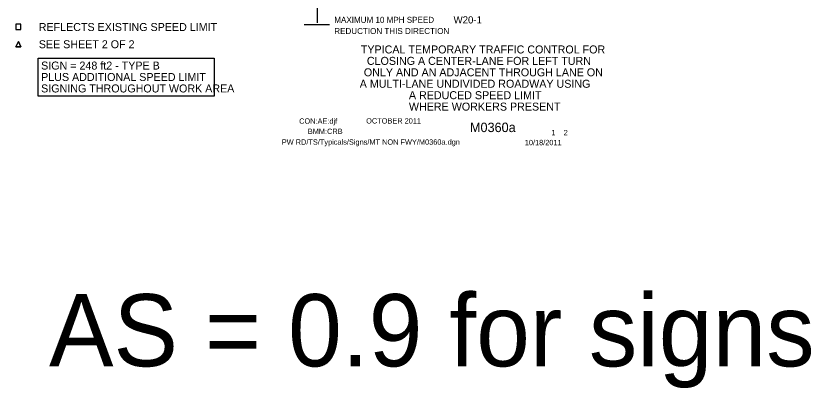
# Model space of a CAD drawing. Extents: x 16730 to 18475, y 5651 to 6927.
# Drawn here: x 16762 to 17686, y 5651 to 6084 of the extents above; entities that cross this region are included whole.
import ezdxf

# ---------------------------------------------------------------- set-up
doc = ezdxf.new("R2010")
doc.units = 0
for name, color, linetype in [('BORDER_SIGNAL_WO', 7, 'Continuous'), ('TRAFFIC_SIGNS_PR', 7, 'Continuous'), ('TYPICAL_TEXT_DIMEN_EX', 7, 'Continuous'), ('TYPICAL_TEXT_DIMEN_PR', 7, 'Continuous')]:
    doc.layers.add(name, color=color, linetype=linetype)

msp = doc.modelspace()

# ---------------------------------------------------------------- linework, layer by layer
at = {"layer": 'TRAFFIC_SIGNS_PR'}
msp.add_lwpolyline([(16761.51, 6067.78), (16767.11, 6067.78), (16767.11, 6073.95), (16761.51, 6073.95)], close=True, dxfattribs=at)
for points in [[(16764.35, 6053.92), (16761.56, 6047.75)], [(16761.56, 6047.75), (16764.35, 6053.92)], [(16767.15, 6047.75), (16764.35, 6053.92)], [(16764.35, 6053.92), (16767.15, 6047.75)], [(16761.56, 6047.75), (16767.15, 6047.75)], [(16767.15, 6047.75), (16761.56, 6047.75)]]:
    msp.add_lwpolyline(points, dxfattribs=at)
at = {"layer": 'TYPICAL_TEXT_DIMEN_EX'}
msp.add_lwpolyline([(16787.48, 6034.22), (16991.76, 6034.22), (16991.76, 5990.25), (16787.48, 5990.25)], close=True, dxfattribs=at)
at = {"layer": 'TYPICAL_TEXT_DIMEN_PR'}
for p, q in [((17111.86, 6075.55), (17111.86, 6092.68)), ((17126.03, 6073.05), (17096.59, 6073.05))]:
    msp.add_line(p, q, dxfattribs=at)

# ---------------------------------------------------------------- texts
at = {"layer": 'BORDER_SIGNAL_WO'}
for s, height, p in [('TYPICAL TEMPORARY TRAFFIC CONTROL FOR', 9.3, (17162.41, 6039.87)), ('CLOSING A CENTER-LANE FOR LEFT TURN', 9.3, (17169.41, 6026.57)), ('ONLY AND AN ADJACENT THROUGH LANE ON', 9.3, (17165.91, 6013.27)), ('A MULTI-LANE UNDIVIDED ROADWAY USING ', 9.3, (17161.11, 5999.97)), ('A REDUCED SPEED LIMIT', 9.3, (17218.28, 5986.67)), ('WHERE WORKERS PRESENT', 9.3, (17218.28, 5973.37)), ('CON:AE:djf', 6.2, (17090.69, 5958.06)), ('    OCTOBER 2011    ', 6.2, (17159.08, 5958.34)), ('BMM:CRB   ', 6.2, (17100.81, 5946.17)), ('    M0360a   ', 11, (17272.86, 5948.38)), (' 1    2 ', 6.2, (17381.45, 5944.7)), ('PW RD/TS/Typicals/Signs/MT NON FWY/M0360a.dgn     ', 6.2, (17070.55, 5933.71)), ('10/18/2011    ', 6.2, (17352.93, 5933.13))]:
    msp.add_text(s, height=height, dxfattribs=at).set_placement(p)
at = {"layer": 'TRAFFIC_SIGNS_PR'}
msp.add_text('W20-1', height=8.37, dxfattribs=at).set_placement((17270.17, 6074.74))
at = {"layer": 'TYPICAL_TEXT_DIMEN_EX'}
for s, p in [('REFLECTS EXISTING SPEED LIMIT', (16788.06, 6065.95)), ('SEE SHEET 2 OF 2', (16788.11, 6045.91)), ('SIGN = 248 ft2 - TYPE B', (16790.82, 6021.11)), ('PLUS ADDITIONAL SPEED LIMIT', (16790.82, 6007.81)), ('SIGNING THROUGHOUT WORK AREA', (16790.82, 5994.51))]:
    msp.add_text(s, height=9.3, dxfattribs=at).set_placement(p)
at = {"layer": 'TYPICAL_TEXT_DIMEN_PR'}
for s, height, p in [('MAXIMUM 10 MPH SPEED', 7, (17131.55, 6075.47)), ('REDUCTION THIS DIRECTION', 7, (17131.55, 6062.47)), ('AS = 0.9 for signs', 84, (16800.02, 5675.86))]:
    msp.add_text(s, height=height, dxfattribs=at).set_placement(p)

doc.saveas('drawing.dxf')
